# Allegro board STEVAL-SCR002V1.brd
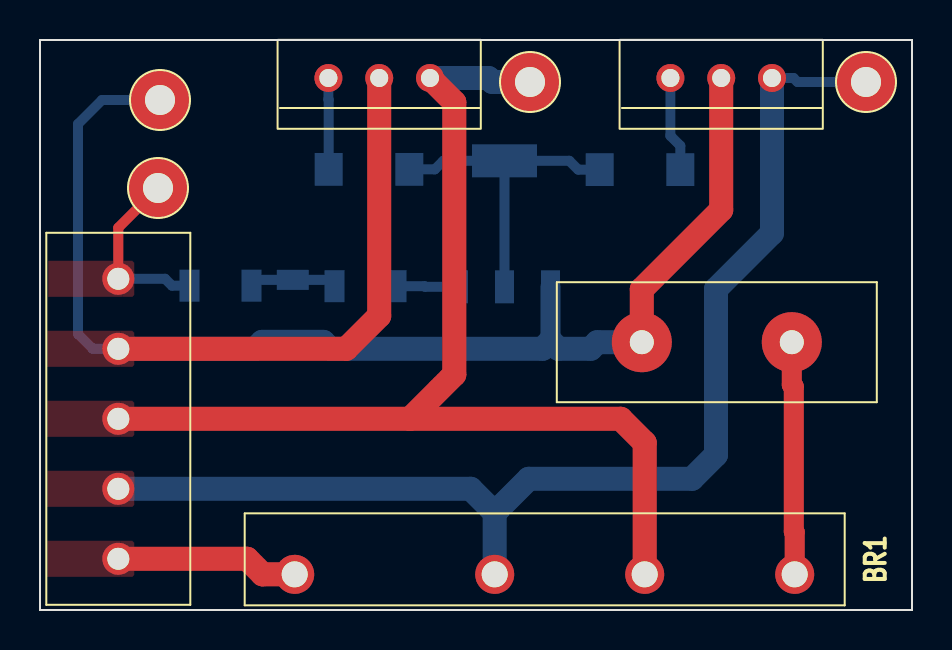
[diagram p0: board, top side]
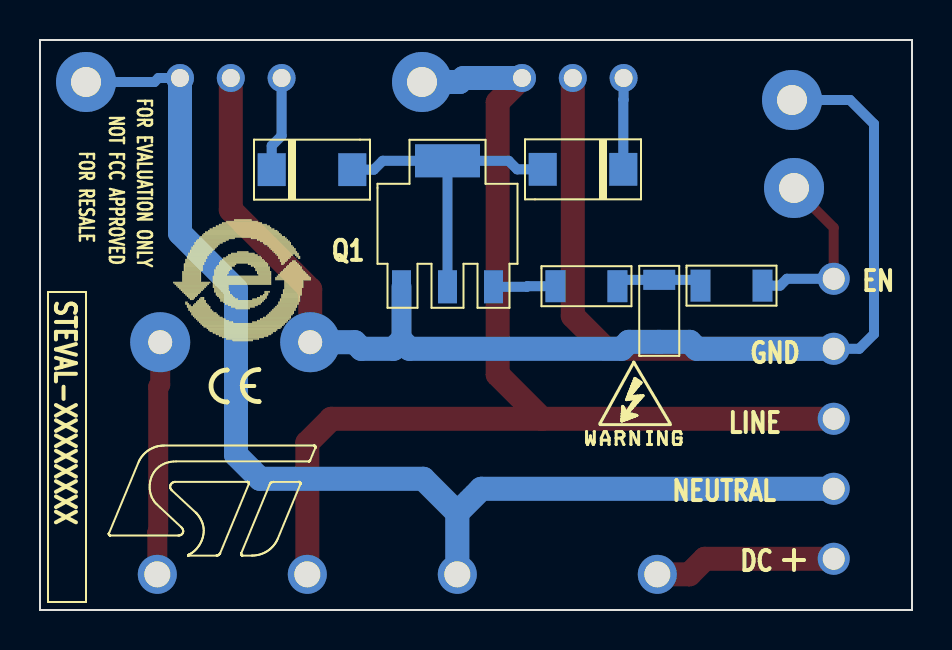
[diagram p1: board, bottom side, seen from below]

Outline 43.6 x 28.5 mm; copper layers: TOP, BOTTOM. Coordinates in mm from the lower left corner of the outline.
Outline path: 0,28.5 43.6,28.5 43.6,0 0,0 0,28.5

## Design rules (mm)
constraint set DEFAULT: min track width 0.3

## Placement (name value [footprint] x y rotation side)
AC_L  test_point_small  [TEST_POINT]  24.5 26.4 0 top
BR1  -  [GBJ1006]  12.73 1.78 0 top
C1  10nF  [CMS1206]  12.64 14.96 270 bottom
D1  STTH110  [SMA]  16.45 22.03 0 bottom
D2  STTH110  [SMA]  30 22.02 180 bottom
EN  test_point_small  [TEST_POINT]  5.9 21.1 0 top
GND  test_point_small  [TEST_POINT]  6 25.5 0 top
J1  conn_5_pts  [CON_5PTS_RS_PAS3_5MM]  3.92 9.56 90 top
NOREF  -  []  43.6 0 90 top
NOREF#2  -  []  0 28.5 0 top
NTC1  2R2_7A  [NTC_S238_EPCOS]  33.84 13.39 0 top
Q1  Z0110MN  [SOT230P700X180-4N]  23.22 19.31 90 bottom
R1  47  [CMS1206]  9.03 16.22 0 bottom
R2  47  [CMS1206]  16.28 16.19 0 bottom
TP3  test_point_small  [TEST_POINT]  41.3 26.4 0 top
X1  TN1205H-6G  [TO220AB]  19.5 26.6 0 top
X2  TN1205H-6G  [TO220AB]  36.6 26.6 0 top

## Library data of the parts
AC_L EN GND TP3 = test_point_small: tolerance: ü
BR1 = GBJ1006: tolerance: ü
C1 = capa_Y2_470pf: tolerance: ü
D1 D2 = STTH110: tolerance: ü
J1 = conn_5_pts: tolerance: ü
NTC1 = R_0: tolerance: ü
Q1 = Z0110MN_2: tolerance: ü
R1 R2 = R: tolerance: ü
X1 X2 = TN1205H-6G_0: tolerance: ü

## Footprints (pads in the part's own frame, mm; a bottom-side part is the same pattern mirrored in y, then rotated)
CMS1206
  rect 1x1.6 smd: 1(-1.55,0) 2(1.55,0)
CON_5PTS_RS_PAS3_5MM
  round 1.6 hole 1.1: 1(-7,0) 2(-3.5,0) 3(0,0) 4(3.5,0) 5(7,0)
GBJ1006
  round 1.95 hole 1.3: 1(0,0) 2(10,0) 3(17.5,0) 4(25,0)
NTC_S238_EPCOS
  round 3 hole 1.2: 1(-3.75,0) 2(3.75,0)
SMA
  rect 1.4x1.64 smd: 1(-2.015,0) 2(2.015,0)
SOT230P700X180-4N
  rect 1.65x0.95 smd: 1(-3.15,2.3) 2(-3.15,0) 3(-3.15,-2.3)
  rect 1.65x3.25 smd: 4(3.15,0)
TEST_POINT
  round 3 hole 1.5: 1(0,0)
TO220AB
  round 1.4 hole 0.9: 1(0,0) 2(-2.54,0) 3(-5.08,0)

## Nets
GND_SIGNAL: C1.2 GND.1(A) J1.4 NTC1.1 Q1.1 X1.2 X2.2
AC_L: AC_L.1(A) BR1.3(~_2) J1.3 X1.1(K)
AC_N: BR1.2 J1.2 TP3.1(A) X2.1(K)
GATE: Q1.3(G) R2.2
N7629489: D1.2 D2.2 Q1.2 Q1.4
N7631947: BR1.4 NTC1.2
N7637748: BR1.1 J1.1
N7638738: C1.1 R1.2 R2.1
N7639486: EN.1(A) J1.5 R1.1
N76370501: D1.1(K) X1.3
N76371101: D2.1(K) X2.3

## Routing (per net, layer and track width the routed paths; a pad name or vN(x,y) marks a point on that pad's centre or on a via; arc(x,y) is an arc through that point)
GND_SIGNAL: length 87.5
  TOP w1.2: 16.96,26.6 16.96,14.71 15.32,13.06 J1.4 ; NTC1.1 30.09,16.04 34.06,20 34.06,26.6
  BOTTOM w0.5: J1.4 2.64,13.06 1.9,13.8 1.9,24.3 3.1,25.5 GND.1
  BOTTOM w1: 25.52,13.46 Q1.1
  BOTTOM w1.2: NTC1.1 27.86,13.39 27.53,13.06 25.92,13.06 25.52,13.46 25.13,13.06 14.51,13.06 14.16,13.41 C1.2 11.11,13.41 10.76,13.06 J1.4
AC_L: length 56.9
  TOP w1.2: X1.1 20.71,25.38 20.71,11.78 18.5,9.56 ; 18.5,9.56 29.03,9.56 30.23,8.36 BR1.3 ; 18.5,9.56 J1.3
  BOTTOM w1.2: AC_L.1 22.62,26.4 22.42,26.6 X1.1
AC_N: length 59.4
  BOTTOM w0.5: TP3.1 37.88,26.4 37.68,26.6 X2.1
  BOTTOM w1.2: 22.73,4.86 21.54,6.06 J1.2 ; 22.73,4.86 BR1.2 ; 22.73,4.86 24.43,6.56 32.6,6.56 33.8,7.76 33.8,16.04 36.6,18.84 X2.1
GATE: length 3.1
  BOTTOM w0.5: Q1.3 19.26,16.16 19.23,16.19 R2.2
N7629489: length 16.2
  BOTTOM w0.5: Q1.2 Q1.4 ; Q1.4 20.17,22.46 19.74,22.03 D1.2 ; Q1.4 26.47,22.46 26.91,22.02 D2.2
N7631947: length 11.7
  TOP w1: NTC1.2 37.59,11.26 37.69,11.16 37.69,3.93 37.73,3.88 BR1.4
N7637748: length 9.1
  TOP w1.2: J1.1 10.36,2.56 11.13,1.78 BR1.1
N7638738: length 4.4
  BOTTOM w0.5: R1.2 10.87,16.51 C1.1 14.41,16.51 R2.1
N7639486: length 9.1
  TOP w0.5: EN.1 3.92,19.11 J1.5
  BOTTOM w0.5: R1.1 6.6,16.22 6.26,16.56 J1.5
N76370501: length 4.6
  BOTTOM w0.5: D1.1 14.43,25.51 14.42,25.52 X1.3
N76371101: length 4.8
  BOTTOM w0.5: 31.52,26.6 31.52,23.71 32.02,23.21 D2.1

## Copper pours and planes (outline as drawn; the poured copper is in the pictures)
GND_SIGNAL on TOP: 4.01,13.96 4.62,13.96 4.71,13.86 4.71,12.26 4.62,12.16 4.01,12.16
GND_SIGNAL on TOP: 0.31,12.16 0.31,13.96 4.01,13.96 4.01,12.16
AC_L on TOP: 4.01,10.46 4.62,10.46 4.71,10.36 4.71,8.76 4.62,8.66 4.01,8.66
AC_L on TOP: 0.31,8.66 0.31,10.46 4.01,10.46 4.01,8.66
AC_N on TOP: 4.01,6.96 4.62,6.96 4.71,6.86 4.71,5.26 4.62,5.16 4.01,5.16
AC_N on TOP: 0.31,5.16 0.31,6.96 4.01,6.96 4.01,5.16
N7637748 on TOP: 0.31,1.66 0.31,3.46 4.01,3.46 4.01,1.66
N7637748 on TOP: 4.01,3.46 4.62,3.46 4.71,3.36 4.71,1.76 4.62,1.66 4.01,1.66
N7639486 on TOP: 4.12,15.66 4.62,15.66 4.71,15.76 4.71,17.36 4.62,17.46 4.12,17.46
N7639486 on TOP: 0.42,15.66 0.42,17.46 4.12,17.46 4.12,15.66

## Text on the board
Ref Des/Silkscreen Bottom: FOR EVALUATION ONLY | NOT FCC APPROVED | FOR RESALE | EN | GND | DC | LINE | NEUTRAL | STEVAL-XXXXXXXX
